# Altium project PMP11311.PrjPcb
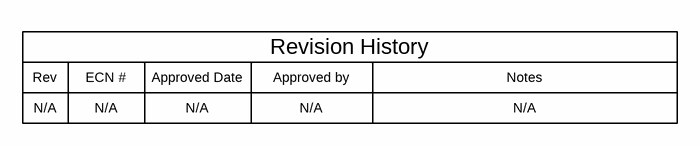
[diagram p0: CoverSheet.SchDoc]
TID: PMP11311; TechSupport: http://www.ti.com/support; SCH_Rev: E1; PRJ_Title: PMP11311; PRJ_Number: PMP11311; PRJ_Engineer: Albert Marco; PRJ_Customer: Public Release; PCB_Rev: E1; PCB_Layout: Albert Marco; EVM_Orderable: N/A; CopyrightYear: 2015
4 sheets, 83 parts. Net scope: flat (ports and power ports of the same name join across sheets).
Board file: PMP11311.PcbDoc
Sheets:
  CoverSheet.SchDoc
  PMP11311_SCH.SchDoc
  PMP11311_charger.SchDoc
  PMP11311_Hardware.SchDoc

## Sheet CoverSheet.SchDoc
size 431 x 279 mm; Date: Not shown in title block; ApprovedBy: Not shown in title block; CheckedBy: Not shown in title block; Author: Not shown in title block; CompanyName: Not shown in title block; Engineer: Not shown in title block; Organization: Not shown in title block; Address1: Not shown in title block; Address2: Not shown in title block; Address3: Not shown in title block; Address4: Not shown in title block; DocumentNumber: 1; Revision: Use project parameter SCH_Rev; SheetNumber: 1; SheetTotal: 3; PageSetup: Record=PageOptions¦CenterHorizontal=True¦CenterVertical=True¦PrintScale=1.00¦XCorrection=1.00¦YCorrection=1.00¦PrintKind=0¦BorderSize=5000000¦LeftOffset=0¦BottomOffset=0¦Orientation=2¦PaperLength=1000¦PaperWidth=1000¦Scale=100¦PaperSource=15¦PrintQuality=600¦MediaType=1¦DitherType=10¦PaperKind=Letter¦PrintScaleMode=1

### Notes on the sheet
- Rev
- N/A
- ECN #
- Approved Date
- Approved by
- Revision History
- Notes

## Sheet PMP11311_SCH.SchDoc
size 431 x 279 mm; Date: Not shown in title block; ApprovedBy: Not shown in title block; CheckedBy: Not shown in title block; Author: Not shown in title block; CompanyName: Not shown in title block; Engineer: Not shown in title block; Organization: Not shown in title block; Address1: Not shown in title block; Address2: Not shown in title block; Address3: Not shown in title block; Address4: Not shown in title block; DocumentNumber: 1; Revision: Use project parameter SCH_Rev; SheetNumber: 2; SheetTotal: 3; PageSetup: Record=PageOptions¦CenterHorizontal=True¦CenterVertical=True¦PrintScale=1.00¦XCorrection=1.00¦YCorrection=1.00¦PrintKind=0¦BorderSize=5000000¦LeftOffset=0¦BottomOffset=0¦Orientation=2¦PaperLength=1000¦PaperWidth=1000¦Scale=100¦PaperSource=15¦PrintQuality=600¦MediaType=1¦DitherType=10¦PaperKind=Letter¦PrintScaleMode=1
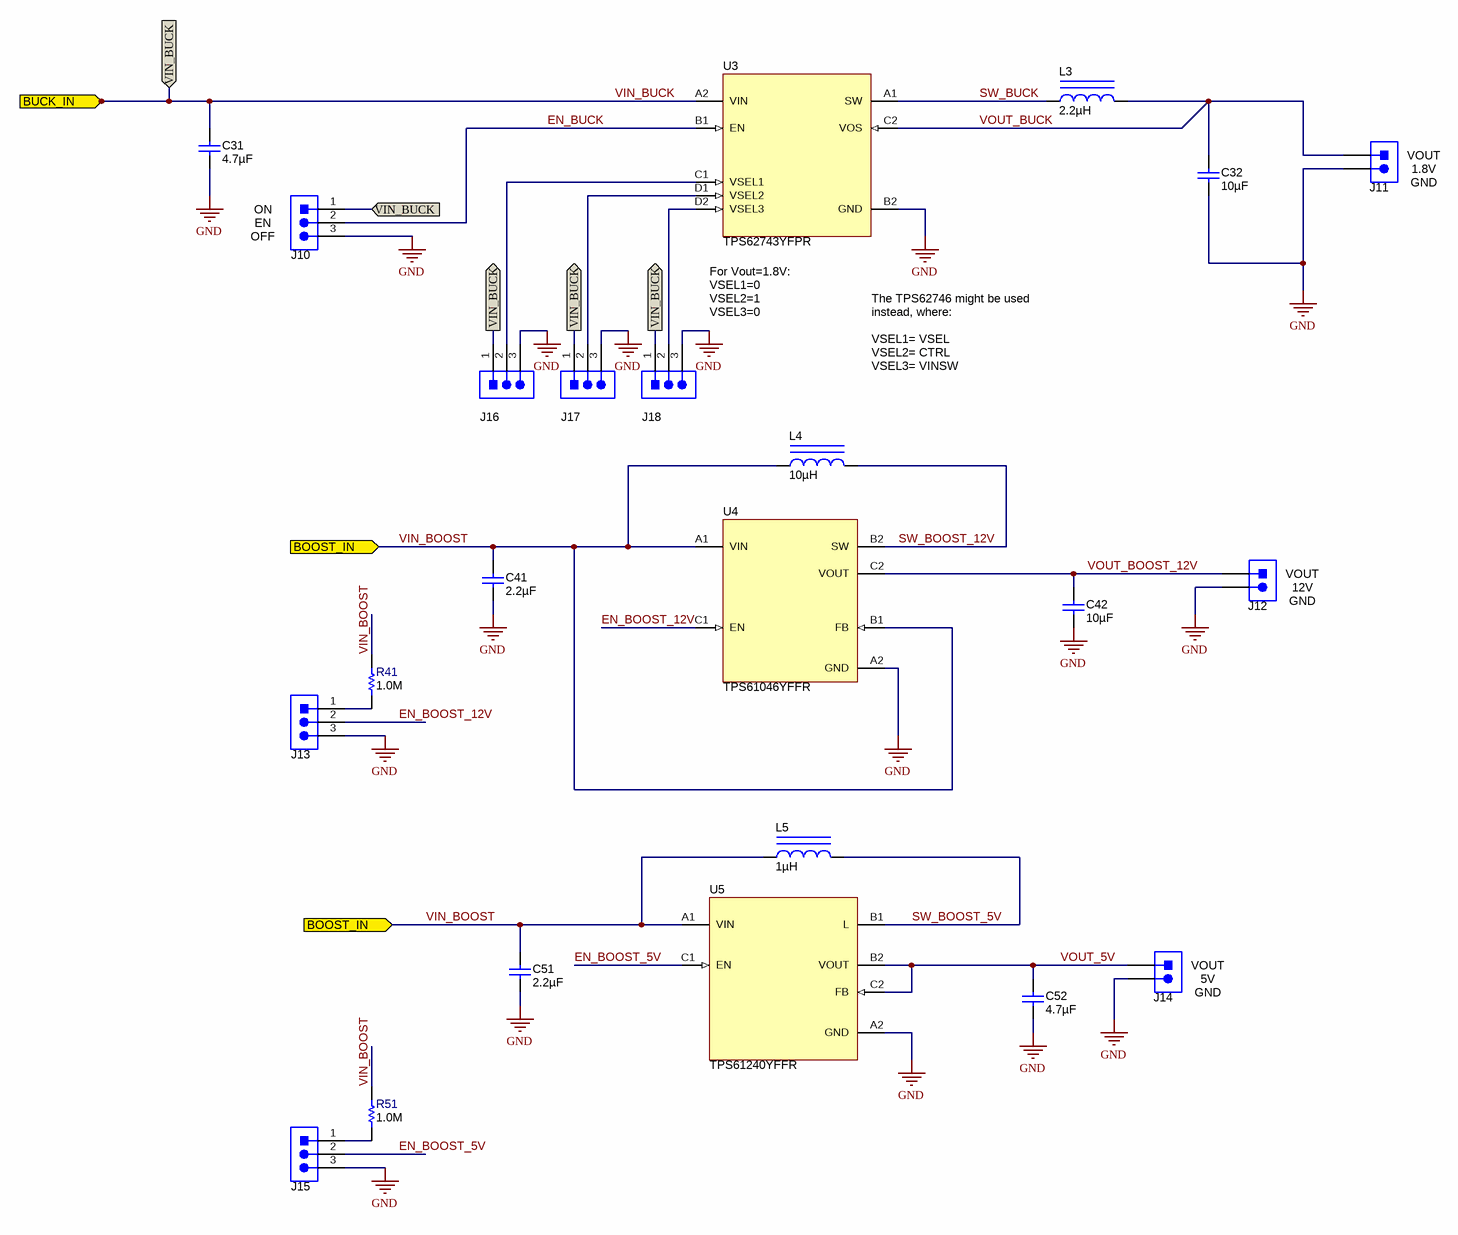
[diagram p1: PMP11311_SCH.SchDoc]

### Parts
C31  ValueDisplayed: 4.7µF  [0402S]  (hidden comment: GRM155R61C475ME15)
C32  ValueDisplayed: 10µF  [0402S]  (hidden comment: GRM155R60J106ME11)
C41  ValueDisplayed: 2.2µF  [0402S]  (hidden comment: GRM155R61A225ME95)
C42  ValueDisplayed: 10µF  [0603S]  (hidden comment: GRM188R61C106MAALD)
C51  ValueDisplayed: 2.2µF  [0402S]  (hidden comment: CL05A225KQ5NNNC)
C52  ValueDisplayed: 4.7µF  [0402S]  (hidden comment: C1005X5R1A475K050BC)
J10  PEC03SAAN  [CONN_PEC03SAAN]  (value not drawn)
J11  PEC02SAAN  [CONN_PEC02SAAN]  (value not drawn)
J12  PEC02SAAN  [CONN_PEC02SAAN]  (value not drawn)
J13  PEC03SAAN  [CONN_PEC03SAAN]  (value not drawn)
J14  PEC02SAAN  [CONN_PEC02SAAN]  (value not drawn)
J15  PEC03SAAN  [CONN_PEC03SAAN]  (value not drawn)
J16  PEC03SAAN  [CONN_PEC03SAAN]  (value not drawn)
J17  PEC03SAAN  [CONN_PEC03SAAN]  (value not drawn)
J18  PEC03SAAN  [CONN_PEC03SAAN]  (value not drawn)
L3  ValueDisplayed: 2.2µH  [DFE201210U]  (hidden comment: DFE201210U-2R2M=P2)
L4  ValueDisplayed: 10µH  [VLS252010HBX]  (hidden comment: VLS252010HBX-100M-1)
L5  ValueDisplayed: 1µH  [MDT2012]  (hidden comment: MDT2012-CH1R0M)
R41  ValueDisplayed: 1.0M  [0603S]  (hidden comment: CRCW06031M00JNEA)
R51  ValueDisplayed: 1.0M  [0603S]  (hidden comment: CRCW06031M00JNEA)
U3  TPS62743YFPR  [YFP0008AGAC]
U4  TPS61046YFFR  [YFF0006AAAA]
U5  TPS61240YFFR  [YFF0006AEAE]

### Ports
BOOST_IN (in), BUCK_IN (in), VIN_BUCK

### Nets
GND: C31.2 C32.2 C41.2 C42.2 C51.2 C52.2 J10.3 J11.2 J12.2 J13.3 J14.2 J15.3 J16.3 J17.3 J18.3 U3.B2(GND) U4.A2(GND) U5.A2(GND)
EN_BOOST_5V: J15.2 U5.C1(EN)
EN_BOOST_12V: J13.2 U4.C1(EN)
EN_BUCK: J10.2 U3.B1(EN)
SW_BOOST_5V: L5.2 U5.B1(L)
SW_BOOST_12V: L4.2 U4.B2(SW)
SW_BUCK: L3.1 U3.A1(SW)
VIN_BOOST: C31.1 C41.1 C51.1 J10.1 J16.1 J17.1 J18.1 L4.1 L5.1 R41.2 R51.2 U3.A2(VIN) U4.A1(VIN) U4.B1(FB) U5.A1(VIN) ; port BOOST_IN, port BUCK_IN, port VIN_BUCK  [also labelled VIN_BUCK]  [project net PMID]
VOUT_5V: C52.1 J14.1 U5.B2(VOUT) U5.C2(FB)
VOUT_BOOST_12V: C42.1 J12.1 U4.C2(VOUT)
VOUT_BUCK: C32.1 J11.1 L3.2 U3.C2(VOS)
NetJ13_1: J13.1 R41.1
NetJ15_1: J15.1 R51.1
NetJ16_2: J16.2 U3.C1(VSEL1)
NetJ17_2: J17.2 U3.D1(VSEL2)
NetJ18_2: J18.2 U3.D2(VSEL3)

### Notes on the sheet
- (near J11) VOUT
- (near J11) 1.8V
- ON
- (near J10) EN
- (near J10) OFF
- (near J11) GND
- For Vout=1.8V:
  VSEL1=0
  VSEL2=1
  VSEL3=0
- The TPS62746 might be used instead, where:
  VSEL1= VSEL
  VSEL2= CTRL
  VSEL3= VINSW
- (near J12) VOUT
- (near J12) GND
- (near J12) 12V
- (near J14) VOUT
- (near J14) 5V
- (near J14) GND

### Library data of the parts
C31 = GRM155R61C475ME15: CAP, CERM, 4.7 µF, 16 V, +/- 20%, X5R, 0402; Manufacturer: MuRata; Polarized: N; CompType: Capacitor; Value: 4.7uF; U/M: EA; Cap_F: 0.0000047; Tolerance_%: 20; Value1: Unknown; VDC_V: 16; Value2: 16V; TaMin_C: -55; TaMax_C: 85; Cap_Case: 0402
C32 = GRM155R60J106ME11: CAP, CERM, 10 µF, 6.3 V, +/- 20%, X5R, 0402; Manufacturer: MuRata; Polarized: N; CompType: Capacitor; Value: 10uF; U/M: EA; Cap_F: 0.00001; Tolerance_%: 20; Value1: Unknown; VDC_V: 6.3; Value2: 6.3V; TaMin_C: -55; TaMax_C: 85; Cap_Case: 0402
C41 = GRM155R61A225ME95: CAP, CERM, 2.2 µF, 10 V, +/- 20%, X5R, 0402; Manufacturer: MuRata; Polarized: N; CompType: Capacitor; Value: 2.2uF; U/M: EA; Cap_F: 0.0000022; Tolerance_%: 20; Value1: Unknown; VDC_V: 10; Value2: 10V; TaMin_C: -55; TaMax_C: 85; Cap_Case: 0402; AEC Category: Q200
C42 = GRM188R61C106MAALD: CAP, CERM, 10 µF, 16 V, +/- 20%, X5R, 0603; Manufacturer: MuRata; Polarized: N; CompType: Capacitor; Value: 10uF; U/M: EA; Cap_F: 0.00001; Tolerance_%: 20; Value1: Unknown; VDC_V: 16; Value2: 16V; TaMin_C: -55; TaMax_C: 85; Cap_Case: 0603; AEC Category: Q200
C51 = CL05A225KQ5NNNC: CAP, CERM, 2.2 µF, 6.3 V, +/- 10%, X5R, 0402; Manufacturer: Samsung; Polarized: N; CompType: Capacitor; Value: 2.2uF; U/M: EA; Cap_F: 0.0000022; Tolerance_%: 10; Value1: Unknown; VDC_V: 6.3; Value2: 6.3V; TaMin_C: -55; TaMax_C: 85; Cap_Case: 0402; AEC Category: Q200
C52 = C1005X5R1A475K050BC: CAP, CERM, 4.7 µF, 10 V, +/- 10%, X5R, 0402; Manufacturer: TDK; Polarized: N; CompType: Capacitor; Value: 4.7uF; U/M: EA; Cap_F: 0.0000047; Tolerance_%: 10; Value1: Unknown; Value2: 10V; TaMin_C: -55; TaMax_C: 85; Cap_Case: 0402; AEC Category: Q200
J10 J13 J15-J18 = PEC03SAAN: Header, 100mil, 3x1, Tin, TH; Manufacturer: Sullins Connector Solutions; SymbolCreator: a0799628; U/M: EA
J11 J12 J14 = PEC02SAAN: Header, 100mil, 2x1, Tin plated, TH; Manufacturer: Sullins Connector Solutions; SymbolCreator: a0412235; U/M: EA
L3 = DFE201210U-2R2M=P2: Inductor, Shielded, Metal Composite, 2.2 µH, 1.4 A, 0.19 ohm, SMD; Manufacturer: Toko; Value: 2.2uH; Ind_H: 2.2E-6; Imax_A: 1.4; Irms: 1.4A @ 40C rise; Isat: 2.2A @ 30% inductance drop; DCR_ohm: 0.19; Value2: 1.4A
L4 = VLS252010HBX-100M-1: Inductor, Wirewound, Ferrite, 10 µH, 0.68 A, 0.46 ohm, SMD; Manufacturer: TDK; Value: 10uH; Ind_H: 10.0E-6; Imax_A: 0.68; Irms: 0.68A @ 40C rise; Isat: 0.95A @ 30% inductance drop; DCR_ohm: 0.46; Value2: 0.68A; AEC Category: Q200; AEC Qualified: N
L5 = MDT2012-CH1R0M: Inductor, Multilayer, 1 µH, 1.4 A, 0.2 ohm, SMD; Manufacturer: Toko; Value: 1uH; Ind_H: 1.0E-6; Imax_A: 1.4; Irms: 1.4A @ 40C rise; DCR_ohm: 0.2; Value1: 0.2 ohm; Value2: 1.4A
R41 R51 = CRCW06031M00JNEA: RES, 1.0 M, 5%, 0.1 W, 0603; Manufacturer: Vishay-Dale; CompType: Resistor; Value: 1.0Meg; Res_ohm: 1000000; Value_Code: 1M00; Tolerance_%: 5; Power_W: 0.1; Value2: 0.1W; VDC_V: 75; TempCo: 200 ppm/C; EIA_Code: E24; U/M: EA
U3 = TPS62743YFPR: 360nA IQ Chip-Scale Step Down Converter, YFP0008AGAC; Alternate PartNumber: TPS62743YFPT; Manufacturer: Texas Instruments; SymbolCreator: Altium; CompType: IC; U/M: EA
U4 = TPS61046YFFR: 28-V Output Voltage Boost Converter in WCSP Package, YFF0006AAAA; Alternate PartNumber: TPS61046YFFT; Manufacturer: Texas Instruments; SymbolCreator: Altium; CompType: IC; U/M: EA
U5 = TPS61240YFFR: 3.5-MHz High Efficiency Step-Up Converter, YFF0006AEAE; Alternate PartNumber: TPS61240YFFT; Manufacturer: Texas Instruments; SymbolCreator: Altium; CompType: IC; U/M: EA

## Sheet PMP11311_charger.SchDoc
size 431 x 279 mm; Date: Not shown in title block; ApprovedBy: Not shown in title block; CheckedBy: Not shown in title block; Author: Not shown in title block; CompanyName: Not shown in title block; Engineer: Not shown in title block; Organization: Not shown in title block; Address1: Not shown in title block; Address2: Not shown in title block; Address3: Not shown in title block; Address4: Not shown in title block; DocumentNumber: 1; Revision: Use project parameter SCH_Rev; SheetNumber: 2; SheetTotal: 3; PageSetup: Record=PageOptions¦CenterHorizontal=True¦CenterVertical=True¦PrintScale=1.00¦XCorrection=1.00¦YCorrection=1.00¦PrintKind=0¦BorderSize=5000000¦LeftOffset=0¦BottomOffset=0¦Orientation=2¦PaperLength=1000¦PaperWidth=1000¦Scale=100¦PaperSource=15¦PrintQuality=600¦MediaType=1¦DitherType=10¦PaperKind=Letter¦PrintScaleMode=1
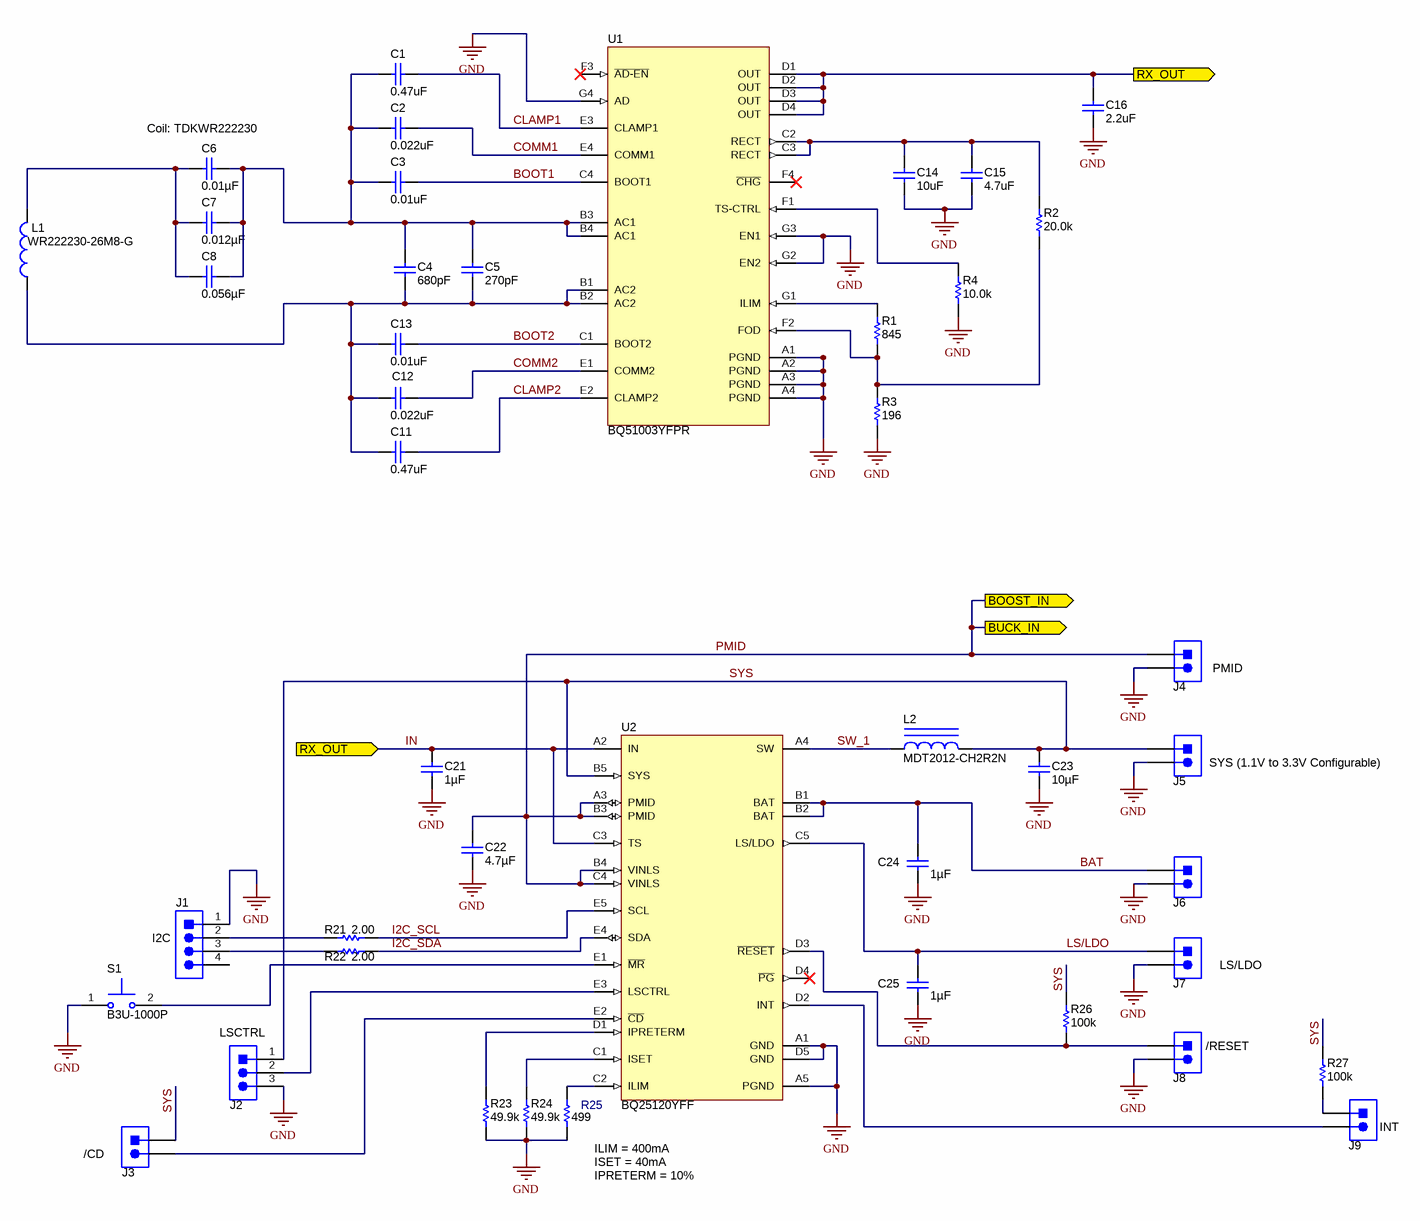
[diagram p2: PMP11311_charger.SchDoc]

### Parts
C1  ValueDisplayed: 0.47uF  [0603S]  (hidden comment: GRM188R71E474KA12D)
C2  ValueDisplayed: 0.022uF  [0402S]  (hidden comment: GRM155R71E223KA61D)
C3  ValueDisplayed: 0.01uF  [0402S]  (hidden comment: GRM155R71E103KA01D)
C4  ValueDisplayed: 680pF  [0402S]  (hidden comment: GRM155R71H681KA01D)
C5  ValueDisplayed: 270pF  [0201]  (hidden comment: GRM033R71E271KA01D)
C6  ValueDisplayed: 0.01µF  [0603S]  (hidden comment: GRM188R71H103KA01D)
C7  ValueDisplayed: 0.012µF  [0603S]  (hidden comment: GRM188R71H123KA01D)
C8  ValueDisplayed: 0.056µF  [0603S]  (hidden comment: GRM188R71H563KA93D)
C11  ValueDisplayed: 0.47uF  [0603S]  (hidden comment: GRM188R71E474KA12D)
C12  ValueDisplayed: 0.022uF  [0402S]  (hidden comment: GRM155R71E223KA61D)
C13  ValueDisplayed: 0.01uF  [0402S]  (hidden comment: GRM155R71E103KA01D)
C14  ValueDisplayed: 10uF  [0603S]  (hidden comment: EMK107BBJ106MA-T)
C15  ValueDisplayed: 4.7uF  [0402L]  (hidden comment: GRM188R61C475KAAJ)
C16  ValueDisplayed: 2.2uF  [0402S]  (hidden comment: C1005X5R1A225K050BC)
C21  ValueDisplayed: 1µF  [0402S]  (hidden comment: C1005X5R1E105K050BC)
C22  ValueDisplayed: 4.7µF  [0402S]  (hidden comment: GRM155R61C475ME11D)
C23  ValueDisplayed: 10µF  [0402S]  (hidden comment: CL05A106MP5NUNC)
C24  ValueDisplayed: 1µF  [0402S]  (hidden comment: GRM155R61A105KE15D)
C25  ValueDisplayed: 1µF  [0402S]  (hidden comment: GRM155R61A105KE15D)
J1  (no value)  [CONN_22-05-3041]
J2  PEC03SAAN  [CONN_PEC03SAAN]  (value not drawn)
J3  PEC02SAAN  [CONN_PEC02SAAN]  (value not drawn)
J4  PEC02SAAN  [CONN_PEC02SAAN]  (value not drawn)
J5  PEC02SAAN  [CONN_PEC02SAAN]  (value not drawn)
J6  PEC02SAAN  [CONN_PEC02SAAN]  (value not drawn)
J7  PEC02SAAN  [CONN_PEC02SAAN]  (value not drawn)
J8  PEC02SAAN  [CONN_PEC02SAAN]  (value not drawn)
J9  PEC02SAAN  [CONN_PEC02SAAN]  (value not drawn)
L1  WR222230-26M8-G  [TDK_WR222230-26M8-G]
L2  MDT2012-CH2R2N  [MDT2012]
R1  ValueDisplayed: 845  [0201M]  (hidden comment: CRCW0201845RFKED)
R2  ValueDisplayed: 20.0k  [0201M]  (hidden comment: CRCW020120K0FKED)
R3  ValueDisplayed: 196  [0201M]  (hidden comment: CRCW0201196RFKED)
R4  ValueDisplayed: 10.0k  [0201M]  (hidden comment: MCR006YRTF1002)
R21  value 2.00  [0603]  (hidden comment: CRCW06032R00FKEA)
R22  value 2.00  [0603]  (hidden comment: CRCW06032R00FKEA)
R23  ValueDisplayed: 49.9k  [0402S]  (hidden comment: CRCW040249K9FKED)
R24  ValueDisplayed: 49.9k  [0402S]  (hidden comment: CRCW040249K9FKED)
R25  value 499  [0402S]  (hidden comment: CRCW0402499RFKED)
R26  ValueDisplayed: 100k  [0402S]  (hidden comment: CRCW0402100KFKED)
R27  ValueDisplayed: 100k  [0402S]  (hidden comment: CRCW0402100KFKED)
S1  B3U-1000P  [SW_B3U-1000P]
U1  BQ51003YFPR  [YFP0028APAL]
U2  BQ25120YFF  [YFF0025AWAW]

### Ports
BOOST_IN (out), BUCK_IN (out), RX_OUT (in), RX_OUT (out)

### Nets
GND: C14.1 C15.2 C16.2 C21.2 C22.2 C23.2 C24.2 C25.2 J1.1 J2.3 J4.2 J5.2 J6.2 J7.2 J8.2 R3.1 R4.1 R23.1 R24.1 R25.2 S1.1 U1.A1(PGND) U1.A2(PGND) U1.A3(PGND) U1.A4(PGND) U1.G2(EN2) U1.G3(EN1) U1.G4(AD) U2.A1(GND) U2.A5(PGND) U2.D5(GND)
BAT: C24.1 J6.1 U2.B1(BAT) U2.B2(BAT)
BOOT1: C3.1 U1.C4(BOOT1)
BOOT2: C13.1 U1.C1(BOOT2)
CLAMP1: C1.1 U1.E3(CLAMP1)
CLAMP2: C11.1 U1.E2(CLAMP2)
COMM1: C2.1 U1.E4(COMM1)
COMM2: C12.1 U1.E1(COMM2)
I2C_SCL: R21.2 U2.E5(SCL)
I2C_SDA: R22.2 U2.E4(SDA)
IN: C16.1 C21.1 U1.D1(OUT) U1.D2(OUT) U1.D3(OUT) U1.D4(OUT) U2.A2(IN) U2.C3(TS) ; port RX_OUT
LS/LDO: C25.1 J7.1 U2.C5(LS/LDO)
PMID: C22.1 J4.1 U2.A3(PMID) U2.B3(PMID) U2.B4(VINLS) U2.C4(VINLS) ; port BUCK_IN, port BOOST_IN
SW_1: L2.1 U2.A4(SW)
SYS: C23.1 J2.1 J3.1 J5.1 L2.2 R26.2 R27.2 U2.B5(SYS)
NetC1_2: C1.2 C2.2 C3.2 C4.1 C5.1 C6.1 C7.1 C8.1 U1.B3(AC1) U1.B4(AC1)
NetC4_2: C4.2 C5.2 C11.2 C12.2 C13.2 L1.1 U1.B1(AC2) U1.B2(AC2)
NetC6_2: C6.2 C7.2 C8.2 L1.2
NetC14_2: C14.2 C15.1 R2.2 U1.C2(RECT) U1.C3(RECT)
NetJ1_2: J1.2 R21.1
NetJ1_3: J1.3 R22.1
NetJ2_2: J2.2 U2.E3(LSCTRL)
NetJ3_2: J3.2 U2.E2(~{CD})
NetJ8_1: J8.1 R26.1 U2.D3(~{RESET})
NetJ9_1: J9.1 R27.1
NetJ9_2: J9.2 U2.D2(INT)
NetR1_1: R1.1 U1.G1(ILIM)
NetR1_2: R1.2 R2.1 R3.2 U1.F2(FOD)
NetR4_2: R4.2 U1.F1(TS-CTRL)
NetR23_2: R23.2 U2.D1(IPRETERM)
NetR24_2: R24.2 U2.C1(ISET)
NetR25_1: R25.1 U2.C2(ILIM)
NetS1_2: S1.2 U2.E1(~{MR})

Not connected (* = marked no-connect by the designer): J1 4; U1 F3(~{AD-EN})* F4(~{CHG})*; U2 D4(~{PG})*

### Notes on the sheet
- (near C6) Coil: TDKWR222230
- (near J4) PMID
- (near J5) SYS (1.1V to 3.3V Configurable)
- (near J1) I2C
- (near J7) LS/LDO
- (near J2) LSCTRL
- (near J8) /RESET
- (near J3) /CD
- (near R25) ILIM = 400mA
  ISET = 40mA
  IPRETERM = 10%
- (near J9) INT

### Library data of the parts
C1 C11 = GRM188R71E474KA12D: CAP, CERM, 0.47uF, 25V, +/-10%, X7R, 0603; Manufacturer: MuRata; Polarized: N; CompType: Capacitor; U/M: EA; Cap_F: 0.00000047; Tolerance_%: 10; Value1: Unknown; VDC_V: 25; TaMin_C: -55; TaMax_C: 125; Cap_Case: 0603
C2 C12 = GRM155R71E223KA61D: CAP, CERM, 0.022uF, 25V, +/-10%, X7R, 0402; Manufacturer: MuRata; Polarized: N; CompType: Capacitor; U/M: EA; Cap_F: 0.000000022; Tolerance_%: 10; Value1: Unknown; VDC_V: 25; TaMin_C: -55; TaMax_C: 125; Cap_Case: 0402
C3 C13 = GRM155R71E103KA01D: CAP, CERM, 0.01uF, 25V, +/-10%, X7R, 0402; Manufacturer: MuRata; Polarized: N; CompType: Capacitor; U/M: EA; Cap_F: 0.00000001; Tolerance_%: 10; Value1: Unknown; VDC_V: 25; TaMin_C: -55; TaMax_C: 125; Cap_Case: 0402
C4 = GRM155R71H681KA01D: CAP, CERM, 680 pF, 50 V, +/- 10%, X7R, 0402; Manufacturer: MuRata; Polarized: N; CompType: Capacitor; Value: 680pF; U/M: EA; Cap_F: 0.00000000068; Tolerance_%: 10; Value1: Unknown; VDC_V: 50; Value2: 50V; TaMin_C: -55; TaMax_C: 125; Cap_Case: 0402; AEC Category: Q200
C5 = GRM033R71E271KA01D: CAP, CERM, 270 pF, 25 V, +/- 10%, X7R, 0201; Manufacturer: MuRata; Polarized: N; CompType: Capacitor; Value: 270pF; U/M: EA; Cap_F: 0.00000000027; Tolerance_%: 10; Value1: Unknown; VDC_V: 25; Value2: 25V; TaMin_C: -55; TaMax_C: 125; AEC Category: Q200
C6 = GRM188R71H103KA01D: CAP, CERM, 0.01 µF, 50 V, +/- 10%, X7R, 0603; Manufacturer: MuRata; Polarized: N; CompType: Capacitor; Value: 0.01uF; U/M: EA; Cap_F: 0.00000001; Tolerance_%: 10; Value1: Unknown; VDC_V: 50; Value2: 50V; TaMin_C: -55; TaMax_C: 125; Cap_Case: 0603; AEC Category: Q200
C7 = GRM188R71H123KA01D: CAP, CERM, 0.012 µF, 50 V, +/- 10%, X7R, 0603; Manufacturer: MuRata; Polarized: N; CompType: Capacitor; Value: 0.012uF; U/M: EA; Cap_F: 0.000000012; Tolerance_%: 10; Value1: Unknown; VDC_V: 50; Value2: 50V; TaMin_C: -55; TaMax_C: 125; Cap_Case: 0603; AEC Category: Q200
C8 = GRM188R71H563KA93D: CAP, CERM, 0.056 µF, 50 V, +/- 10%, X7R, 0603; Manufacturer: MuRata; Polarized: N; CompType: Capacitor; Value: 0.056uF; U/M: EA; Cap_F: 0.000000056; Tolerance_%: 10; Value1: Unknown; VDC_V: 50; Value2: 50V; TaMin_C: -55; TaMax_C: 125; Cap_Case: 0603; AEC Category: Q200
C14 = EMK107BBJ106MA-T: CAP, CERM, 10uF, 16V, +/-20%, X5R, 0603; Manufacturer: Taiyo Yuden; Polarized: N; CompType: Capacitor; U/M: EA; Cap_F: 0.00001; Tolerance_%: 20; Value1: Unknown; VDC_V: 16; TaMin_C: -55; TaMax_C: 85; Cap_Case: 0603
C15 = GRM188R61C475KAAJ: CAP, CERM, 4.7uF, 16V, +/-10%, X5R, 0603; Manufacturer: MuRata; Polarized: N; CompType: Capacitor; U/M: EA; Cap_F: 0.0000047; Tolerance_%: 10; Value1: Unknown; VDC_V: 16; TaMin_C: -55; TaMax_C: 85; Cap_Case: 0603
C16 = C1005X5R1A225K050BC: CAP, CERM, 2.2uF, 10V, +/-10%, X5R, 0402; Manufacturer: TDK; Polarized: N; CompType: Capacitor; U/M: EA; Cap_F: 0.0000022; Tolerance_%: 10; Value1: Unknown; TaMin_C: -55; TaMax_C: 85; Cap_Case: 0402
C21 = C1005X5R1E105K050BC: CAP, CERM, 1 µF, 25 V, +/- 10%, X5R, 0402; Manufacturer: TDK; Polarized: N; CompType: Capacitor; Value: 1uF; U/M: EA; Cap_F: 0.000001; Tolerance_%: 10; Value1: Unknown; VDC_V: 25; Value2: 25V; TaMin_C: -55; TaMax_C: 80; Cap_Case: 0402
C22 = GRM155R61C475ME11D: CAP, CERM, 4.7 µF, 16 V, +/- 20%, X5R, 0402; Manufacturer: MuRata; Polarized: N; CompType: Capacitor; Value: 4.7uF; U/M: EA; Cap_F: 0.0000047; Tolerance_%: 20; Value1: Unknown; VDC_V: 16; Value2: 16V; TaMin_C: -55; TaMax_C: 85; Cap_Case: 0402
C23 = CL05A106MP5NUNC: CAP, CERM, 10 µF, 10 V, +/- 20%, X5R, 0402; Manufacturer: Samsung Electro-Mechanics; Polarized: N; CompType: Capacitor; Value: 10uF; U/M: EA; Cap_F: 0.00001; Tolerance_%: 20; Value1: Unknown; VDC_V: 10; Value2: 10V; TaMin_C: -55; TaMax_C: 85; Cap_Case: 0402
C24 C25 = GRM155R61A105KE15D: CAP, CERM, 1 µF, 10 V, +/- 10%, X5R, 0402; Manufacturer: MuRata; Polarized: N; CompType: Capacitor; Value: 1uF; U/M: EA; Cap_F: 0.000001; Tolerance_%: 10; Value1: Unknown; Value2: 10V; TaMin_C: -55; TaMax_C: 85; Cap_Case: 0402
J1 = 22-05-3041: Header (friction lock), 100mil, 4x1, R/A, TH; Manufacturer: Molex; SymbolCreator: a0412235; U/M: EA
J2 = PEC03SAAN: as J10 on sheet PMP11311_SCH
J3-J9 = PEC02SAAN: as J11 on sheet PMP11311_SCH
L1 = WR222230-26M8-G: Wireless Power Charging Receiver Coil; Manufacturer: TDK; CompType: Wireless Charging
L2 = MDT2012-CH2R2N: Inductor, Multilayer, 2.2 µH, 1.3 A, 0.245 ohm, SMD; Manufacturer: Toko; Value: 2.2uH; Ind_H: 2.2E-6; ValueDisplayed: 2.2µH; Imax_A: 1.3; Irms: 1.3A @ 40C rise; DCR_ohm: 0.245; Value2: 1.3A
R1 = CRCW0201845RFKED: RES, 845, 1%, 0.05 W, 0201; Manufacturer: Vishay-Dale; CompType: Resistor; Value: 845; Value_Code: 845R; Tolerance_%: 1; Power_W: 0.05; Value2: 0.05W; VDC_V: 30; TempCo: 100 ppm/C; EIA_Code: E96; U/M: EA
R2 = CRCW020120K0FKED: RES, 20.0 k, 1%, 0.05 W, 0201; Manufacturer: Vishay-Dale; CompType: Resistor; Value: 20.0k; Res_ohm: 20000; Value_Code: 20k0; Tolerance_%: 1; Power_W: 0.05; Value2: 0.05W; VDC_V: 30; TempCo: 100 ppm/C; EIA_Code: E96; U/M: EA
R3 = CRCW0201196RFKED: RES, 196, 1%, 0.05 W, 0201; Manufacturer: Vishay-Dale; CompType: Resistor; Value: 196; Value_Code: 196R; Tolerance_%: 1; Power_W: 0.05; Value2: 0.05W; VDC_V: 30; TempCo: 100 ppm/C; EIA_Code: E96; U/M: EA
R4 = MCR006YRTF1002: RES, 10.0 k, 1%, 0.05 W, 0201; Manufacturer: Rohm; CompType: Resistor; Res_ohm: 10000; Value: 10.0k; Value_Code: 10k0; Tolerance_%: 1; Power_W: 0.05; Value2: 0.05W; VDC_V: 25; TempCo: 250 ppm/C; EIA_Code: E96; U/M: EA
R21 R22 = CRCW06032R00FKEA: RES, 2.00 ohm, 1%, 0.1W, 0603; Manufacturer: Vishay-Dale; CompType: Resistor; Res_ohm: 2; Value_Code: 2R00; Tolerance_%: 1; Power_W: 0.1; VDC_V: 75; TempCo: 100 ppm/C; EIA_Code: E96; U/M: EA
R23 R24 = CRCW040249K9FKED: RES, 49.9 k, 1%, 0.063 W, 0402; Manufacturer: Vishay-Dale; CompType: Resistor; Value: 49.9k; Res_ohm: 49900; Value_Code: 49k9; Tolerance_%: 1; Power_W: 0.063; Value2: 0.063W; VDC_V: 50; TempCo: 100 ppm/C; EIA_Code: E96; U/M: EA
R25 = CRCW0402499RFKED: RES, 499 ohm, 1%, 0.063W, 0402; Manufacturer: Vishay-Dale; CompType: Resistor; Value_Code: 499R; Tolerance_%: 1; Power_W: 0.063; VDC_V: 50; TempCo: 100 ppm/C; EIA_Code: E96; U/M: EA
R26 R27 = CRCW0402100KFKED: RES, 100 k, 1%, 0.063 W, 0402; Manufacturer: Vishay-Dale; CompType: Resistor; Value: 100k; Res_ohm: 100000; Tolerance_%: 1; Power_W: 0.063; Value2: 0.063W; VDC_V: 50; TempCo: 100 ppm/C; EIA_Code: E96; U/M: EA
S1 = B3U-1000P: SWITCH TACTILE SPST-NO 0.05A 12V; Manufacturer: Omron Electronic Components; SymbolCreator: a0412235; VDC_V: 12; SwitchFunction: Off-Mom; PositionCount: 1; CurrentRating_mA: 50
U1 = BQ51003YFPR: Highly Integrated Wireless Receiver Qi (WPC v1.1) Compliant Power Supply, YFP0028APAL; Alternate PartNumber: BQ51003YFPT; Manufacturer: Texas Instruments; SymbolCreator: Altium; CompType: IC; U/M: EA
U2 = BQ25120YFF: YFF0025AWAW; Manufacturer: Texas Instruments; Alternate Manufacturer: None; SymbolCreator: x0208326; CompType: IC; U/M: EA

## Sheet PMP11311_Hardware.SchDoc
size 431 x 279 mm; Date: Not shown in title block; ApprovedBy: Not shown in title block; CheckedBy: Not shown in title block; Author: Not shown in title block; CompanyName: Not shown in title block; Engineer: Not shown in title block; Organization: Not shown in title block; Address1: Not shown in title block; Address2: Not shown in title block; Address3: Not shown in title block; Address4: Not shown in title block; DocumentNumber: 1; Revision: Use project parameter SCH_Rev; SheetNumber: 3; SheetTotal: 3; PageSetup: Record=PageOptions¦CenterHorizontal=True¦CenterVertical=True¦PrintScale=1.00¦XCorrection=1.00¦YCorrection=1.00¦PrintKind=0¦BorderSize=5000000¦LeftOffset=0¦BottomOffset=0¦Orientation=2¦PaperLength=1000¦PaperWidth=1000¦Scale=100¦PaperSource=15¦PrintQuality=600¦MediaType=1¦DitherType=10¦PaperKind=Letter¦PrintScaleMode=1
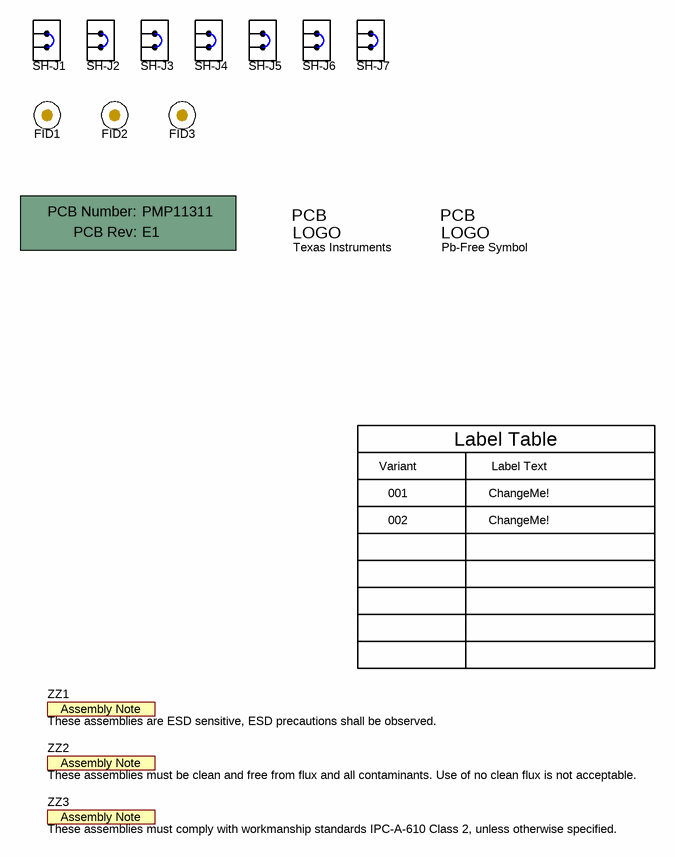
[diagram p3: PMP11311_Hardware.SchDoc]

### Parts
!PCB1  Printed Circuit Board  (value not drawn)  (mechanical)
FID1  Fiducial  [Fiducial10-20]  (value not drawn)
FID2  Fiducial  [Fiducial10-20]  (value not drawn)
FID3  Fiducial  [Fiducial10-20]  (value not drawn)
Logo1  Texas Instruments  [TI_Stacked_Overlay_Small]  (no BOM)
Logo2  Pb-Free Symbol  [Pb-Free_Overlay_Small]  (no BOM)
SH-J1  SNT-100-BK-G  [SNT-100-BK-G]  (value not drawn)
SH-J2  SNT-100-BK-G  [SNT-100-BK-G]  (value not drawn)
SH-J3  SNT-100-BK-G  [SNT-100-BK-G]  (value not drawn)
SH-J4  SNT-100-BK-G  [SNT-100-BK-G]  (value not drawn)
SH-J5  SNT-100-BK-G  [SNT-100-BK-G]  (value not drawn)
SH-J6  SNT-100-BK-G  [SNT-100-BK-G]  (value not drawn)
SH-J7  SNT-100-BK-G  [SNT-100-BK-G]  (value not drawn)
ZZ1  These assemblies are ESD sensitive, ESD precautions shall be observed.  [AssemblyNote]  (no BOM)
ZZ2  These assemblies must be clean and free from flux and all contaminants. Use of no clean flux is not acceptable.  [AssemblyNote]  (no BOM)
ZZ3  These assemblies must comply with workmanship standards IPC-A-610 Class 2, unless otherwise specified.  [AssemblyNote]  (no BOM)

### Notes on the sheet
- Variant
- Label Table
- Label Text
- 001
- 002
- ChangeMe!

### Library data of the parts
!PCB1 = PCB: Manufacturer: Any; PartNumber: PMP11311; SymbolCreator: a0412235
FID1-FID3 = Fiducial: Fiducial mark.  There is nothing to buy or mount.; SymbolCreator: codlsc
Logo1 = TI_Logo: Texas Instrument Corporate Signature; SymbolCreator: codlsc
Logo2 = Pb-Free: SymbolCreator: a0412235
SH-J1-SH-J7 = SNT-100-BK-G: Shunt, 100mil, Gold plated, Black; Manufacturer: Samtec; Alternate Manufacturer: 3M; Alternate PartNumber: 969102-0000-DA; Value: 1x2; Note: You can "mate" this to a header by matching the designator.  i.e. use SH-J3 for header J3
ZZ1-ZZ3 = AssemblyNote: SymbolCreator: codlsc

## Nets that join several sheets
GND: PMP11311_SCH (18 pins), PMP11311_charger (31 pins)
PMID: PMP11311_SCH (15 pins), PMP11311_charger (6 pins)

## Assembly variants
001: not fitted FID1 FID2 FID3 R31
